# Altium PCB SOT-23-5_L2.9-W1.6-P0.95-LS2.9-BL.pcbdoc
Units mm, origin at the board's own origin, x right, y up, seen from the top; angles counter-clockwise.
Board outline 15.66 x 15.9 mm, 2 copper layers (Top Layer, Bottom Layer), stack 0 mm thick; 1 components, 0 nets, 5 pads, 0 vias.
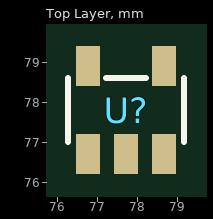
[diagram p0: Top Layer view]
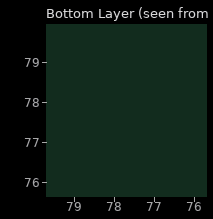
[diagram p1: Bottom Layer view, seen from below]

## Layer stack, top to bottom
Top Layer: signal copper (thickness not stored)
Bottom Layer: signal copper (thickness not stored)

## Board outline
85.51,69.85 69.85,69.85 69.85,85.75 85.51,85.75

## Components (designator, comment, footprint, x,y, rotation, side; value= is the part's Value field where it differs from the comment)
U? "" SOT-23-5_L2.9-W1.6-P0.95-LS2.9-BL 77.71,77.8 r0 top

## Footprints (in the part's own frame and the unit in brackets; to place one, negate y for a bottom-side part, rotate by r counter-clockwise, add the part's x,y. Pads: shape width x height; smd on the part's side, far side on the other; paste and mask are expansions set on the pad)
SOT-23-5_L2.9-W1.6-P0.95-LS2.9-BL [mm]
  rect 0.6x1 smd paste+0 mask+0.05: 1(-0.95,-1.1) 2(0,-1.1) 3(0.95,-1.1) 4(0.95,1.1) 5(-0.95,1.1)
  silkscreen extent -1.45,-0.8 1.45,0.8

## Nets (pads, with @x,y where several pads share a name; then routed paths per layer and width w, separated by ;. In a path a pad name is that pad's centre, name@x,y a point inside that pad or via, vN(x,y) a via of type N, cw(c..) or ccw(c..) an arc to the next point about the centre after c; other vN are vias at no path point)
pads on no net: U?.1 U?.2 U?.3 U?.4 U?.5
